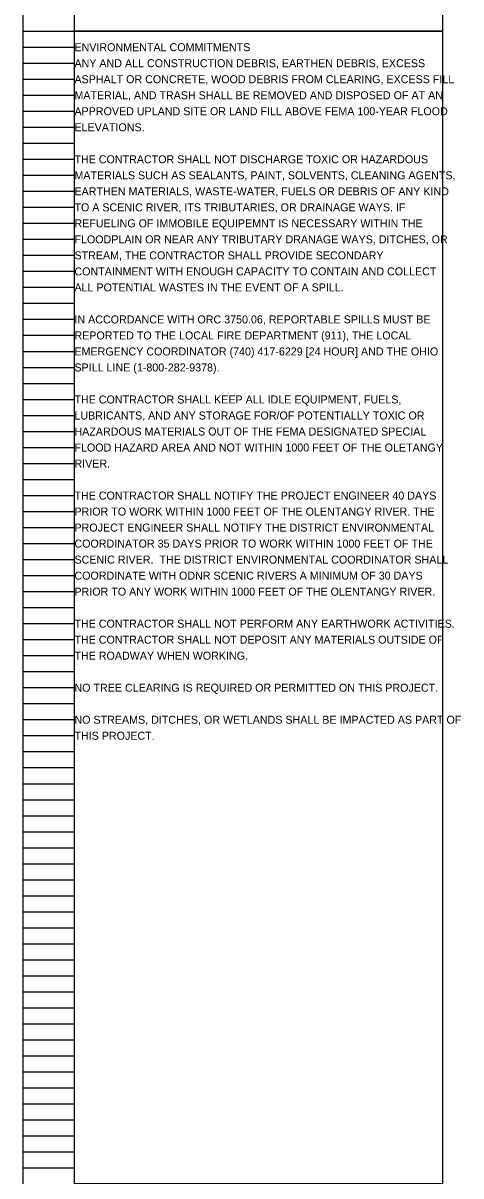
# Model space of a CAD drawing. Extents: x 16463 to 16495, y 5662 to 5823.
# Drawn here: x 16463.05 to 16470.71, y 5742.97 to 5763.13 of the extents above; entities that cross this region are included whole.
import ezdxf

# ---------------------------------------------------------------- set-up
doc = ezdxf.new("R2010")
doc.units = 0
for name, color, linetype in [('Default', 7, 'Continuous'), ('SC_Scratch1', 7, 'Continuous'), ('SH_Data', 7, 'Continuous')]:
    doc.layers.add(name, color=color, linetype=linetype)

msp = doc.modelspace()

# ---------------------------------------------------------------- linework, layer by layer
at = {"layer": 'SC_Scratch1'}
for points in [[(16463.949, 5783.152), (16470.389, 5783.152), (16470.389, 5762.992), (16463.949, 5762.992)], [(16463.949, 5762.992), (16470.389, 5762.992), (16470.389, 5742.832), (16463.949, 5742.832)]]:
    msp.add_lwpolyline(points, close=True, dxfattribs=at)
at = {"layer": 'SH_Data'}
for p, q in [((16463.049, 5762.992), (16463.049, 5783.152)), ((16463.949, 5762.992), (16463.949, 5783.152)), ((16463.049, 5742.832), (16463.049, 5762.992)), ((16463.049, 5762.992), (16463.949, 5762.992)), ((16463.049, 5762.992), (16463.949, 5762.992)), ((16463.949, 5742.832), (16463.949, 5762.992)), ((16463.049, 5762.712), (16463.949, 5762.712)), ((16463.049, 5762.432), (16463.949, 5762.432)), ((16463.049, 5762.152), (16463.949, 5762.152)), ((16463.049, 5761.872), (16463.949, 5761.872)), ((16463.049, 5761.592), (16463.949, 5761.592)), ((16463.049, 5761.312), (16463.949, 5761.312)), ((16463.049, 5761.032), (16463.949, 5761.032)), ((16463.049, 5760.752), (16463.949, 5760.752)), ((16463.049, 5760.472), (16463.949, 5760.472)), ((16463.049, 5760.192), (16463.949, 5760.192)), ((16463.049, 5759.912), (16463.949, 5759.912)), ((16463.049, 5759.632), (16463.949, 5759.632)), ((16463.049, 5759.352), (16463.949, 5759.352)), ((16463.049, 5759.072), (16463.949, 5759.072)), ((16463.049, 5758.792), (16463.949, 5758.792)), ((16463.049, 5758.512), (16463.949, 5758.512)), ((16463.049, 5758.232), (16463.949, 5758.232)), ((16463.049, 5757.952), (16463.949, 5757.952)), ((16463.049, 5757.672), (16463.949, 5757.672)), ((16463.049, 5757.392), (16463.949, 5757.392)), ((16463.049, 5757.112), (16463.949, 5757.112)), ((16463.049, 5756.832), (16463.949, 5756.832)), ((16463.049, 5756.552), (16463.949, 5756.552)), ((16463.049, 5756.272), (16463.949, 5756.272)), ((16463.049, 5755.992), (16463.949, 5755.992)), ((16463.049, 5755.712), (16463.949, 5755.712)), ((16463.049, 5755.432), (16463.949, 5755.432)), ((16463.049, 5755.152), (16463.949, 5755.152)), ((16463.049, 5754.872), (16463.949, 5754.872)), ((16463.049, 5754.592), (16463.949, 5754.592)), ((16463.049, 5754.312), (16463.949, 5754.312)), ((16463.049, 5754.032), (16463.949, 5754.032)), ((16463.049, 5753.752), (16463.949, 5753.752)), ((16463.049, 5753.472), (16463.949, 5753.472)), ((16463.049, 5753.192), (16463.949, 5753.192)), ((16463.049, 5752.912), (16463.949, 5752.912)), ((16463.049, 5752.632), (16463.949, 5752.632)), ((16463.049, 5752.352), (16463.949, 5752.352)), ((16463.049, 5752.072), (16463.949, 5752.072)), ((16463.049, 5751.792), (16463.949, 5751.792)), ((16463.049, 5751.512), (16463.949, 5751.512)), ((16463.049, 5751.232), (16463.949, 5751.232)), ((16463.049, 5750.952), (16463.949, 5750.952)), ((16463.049, 5750.672), (16463.949, 5750.672)), ((16463.049, 5750.392), (16463.949, 5750.392)), ((16463.049, 5750.112), (16463.949, 5750.112)), ((16463.049, 5749.832), (16463.949, 5749.832)), ((16463.049, 5749.552), (16463.949, 5749.552)), ((16463.049, 5749.272), (16463.949, 5749.272)), ((16463.049, 5748.992), (16463.949, 5748.992)), ((16463.049, 5748.712), (16463.949, 5748.712)), ((16463.049, 5748.432), (16463.949, 5748.432)), ((16463.049, 5748.152), (16463.949, 5748.152)), ((16463.049, 5747.872), (16463.949, 5747.872)), ((16463.049, 5747.592), (16463.949, 5747.592)), ((16463.049, 5747.312), (16463.949, 5747.312)), ((16463.049, 5747.032), (16463.949, 5747.032)), ((16463.049, 5746.752), (16463.949, 5746.752)), ((16463.049, 5746.472), (16463.949, 5746.472)), ((16463.049, 5746.192), (16463.949, 5746.192)), ((16463.049, 5745.912), (16463.949, 5745.912)), ((16463.049, 5745.632), (16463.949, 5745.632)), ((16463.049, 5745.352), (16463.949, 5745.352)), ((16463.049, 5745.072), (16463.949, 5745.072)), ((16463.049, 5744.792), (16463.949, 5744.792)), ((16463.049, 5744.512), (16463.949, 5744.512)), ((16463.049, 5744.232), (16463.949, 5744.232)), ((16463.049, 5743.952), (16463.949, 5743.952)), ((16463.049, 5743.672), (16463.949, 5743.672)), ((16463.049, 5743.392), (16463.949, 5743.392)), ((16463.049, 5743.112), (16463.949, 5743.112))]:
    msp.add_line(p, q, dxfattribs=at)

# ---------------------------------------------------------------- texts
at = {"layer": 'Default'}
for s, p in [('ENVIRONMENTAL COMMITMENTS', (16463.949, 5762.64)), ('ANY AND ALL CONSTRUCTION DEBRIS, EARTHEN DEBRIS, EXCESS ', (16463.949, 5762.36)), ('ASPHALT OR CONCRETE, WOOD DEBRIS FROM CLEARING, EXCESS FILL ', (16463.949, 5762.08)), ('MATERIAL, AND TRASH SHALL BE REMOVED AND DISPOSED OF AT AN ', (16463.949, 5761.8)), ('APPROVED UPLAND SITE OR LAND FILL ABOVE FEMA 100-YEAR FLOOD ', (16463.949, 5761.52)), ('ELEVATIONS.', (16463.949, 5761.24)), ('THE CONTRACTOR SHALL NOT DISCHARGE TOXIC OR HAZARDOUS ', (16463.949, 5760.68)), ('MATERIALS SUCH AS SEALANTS, PAINT, SOLVENTS, CLEANING AGENTS, ', (16463.949, 5760.4)), ('EARTHEN MATERIALS, WASTE-WATER, FUELS OR DEBRIS OF ANY KIND ', (16463.949, 5760.12)), ('TO A SCENIC RIVER, ITS TRIBUTARIES, OR DRAINAGE WAYS. IF ', (16463.949, 5759.84)), ('REFUELING OF IMMOBILE EQUIPEMNT IS NECESSARY WITHIN THE ', (16463.949, 5759.56)), ('FLOODPLAIN OR NEAR ANY TRIBUTARY DRANAGE WAYS, DITCHES, OR ', (16463.949, 5759.28)), ('STREAM, THE CONTRACTOR SHALL PROVIDE SECONDARY ', (16463.949, 5759)), ('CONTAINMENT WITH ENOUGH CAPACITY TO CONTAIN AND COLLECT ', (16463.949, 5758.72)), ('ALL POTENTIAL WASTES IN THE EVENT OF A SPILL.', (16463.949, 5758.44)), ('IN ACCORDANCE WITH ORC 3750.06, REPORTABLE SPILLS MUST BE ', (16463.949, 5757.88)), ('REPORTED TO THE LOCAL FIRE DEPARTMENT (911), THE LOCAL ', (16463.949, 5757.6)), ('EMERGENCY COORDINATOR (740) 417-6229 [24 HOUR] AND THE OHIO ', (16463.949, 5757.32)), ('SPILL LINE (1-800-282-9378).', (16463.949, 5757.04)), ('THE CONTRACTOR SHALL KEEP ALL IDLE EQUIPMENT, FUELS, ', (16463.949, 5756.48)), ('LUBRICANTS, AND ANY STORAGE FOR/OF POTENTIALLY TOXIC OR ', (16463.949, 5756.2)), ('HAZARDOUS MATERIALS OUT OF THE FEMA DESIGNATED SPECIAL ', (16463.949, 5755.92)), ('FLOOD HAZARD AREA AND NOT WITHIN 1000 FEET OF THE OLETANGY ', (16463.949, 5755.64)), ('RIVER.', (16463.949, 5755.36)), ('THE CONTRACTOR SHALL NOTIFY THE PROJECT ENGINEER 40 DAYS ', (16463.949, 5754.8)), ('PRIOR TO WORK WITHIN 1000 FEET OF THE OLENTANGY RIVER. THE ', (16463.949, 5754.52)), ('PROJECT ENGINEER SHALL NOTIFY THE DISTRICT ENVIRONMENTAL ', (16463.949, 5754.24)), ('COORDINATOR 35 DAYS PRIOR TO WORK WITHIN 1000 FEET OF THE ', (16463.949, 5753.96)), ('SCENIC RIVER.  THE DISTRICT ENVIRONMENTAL COORDINATOR SHALL ', (16463.949, 5753.68)), ('COORDINATE WITH ODNR SCENIC RIVERS A MINIMUM OF 30 DAYS ', (16463.949, 5753.4)), ('PRIOR TO ANY WORK WITHIN 1000 FEET OF THE OLENTANGY RIVER. ', (16463.949, 5753.12)), ('THE CONTRACTOR SHALL NOT PERFORM ANY EARTHWORK ACTIVITIES. ', (16463.949, 5752.56)), ('THE CONTRACTOR SHALL NOT DEPOSIT ANY MATERIALS OUTSIDE OF ', (16463.949, 5752.28)), ('THE ROADWAY WHEN WORKING.', (16463.949, 5752)), ('NO TREE CLEARING IS REQUIRED OR PERMITTED ON THIS PROJECT.', (16463.949, 5751.44)), ('NO STREAMS, DITCHES, OR WETLANDS SHALL BE IMPACTED AS PART OF ', (16463.949, 5750.88)), ('THIS PROJECT.', (16463.949, 5750.6))]:
    msp.add_text(s, height=0.14, dxfattribs=at).set_placement(p)

doc.saveas('drawing.dxf')
